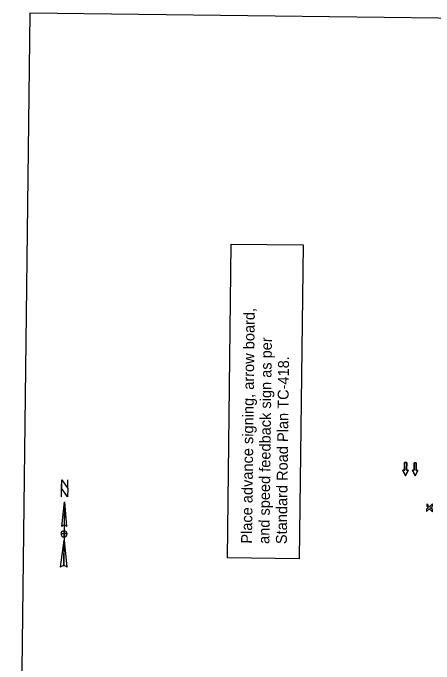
# Model space of a CAD drawing. Extents: x 4959127 to 4960275, y 3872379 to 3884458.
# Drawn here: x 4959256 to 4959738, y 3883713 to 3884458 of the extents above; entities that cross this region are included whole.
import ezdxf

# ---------------------------------------------------------------- set-up
doc = ezdxf.new("R2010")
doc.units = 0
for name, color, linetype in [('Cell', 7, 'Continuous'), ('dsnCellElements', 7, 'Continuous'), ('Level 2', 7, 'Continuous'), ('Level 5', 7, 'Continuous'), ('NamedBoundary', 7, 'Continuous'), ('SheetText', 7, 'Continuous')]:
    doc.layers.add(name, color=color, linetype=linetype)

msp = doc.modelspace()

# ---------------------------------------------------------------- linework, layer by layer
at = {"layer": 'Cell'}
for p, q in [((4959314.62, 3883898.17), (4959313.72, 3883824.93)), ((4959314.62, 3883898.17), (4959317.09, 3883869.97)), ((4959311.46, 3883870.04), (4959311.46, 3883870.04)), ((4959311.57, 3883870.3), (4959312.1, 3883870.88)), ((4959310.19, 3883823.57), (4959314.09, 3883854.51)), ((4959314.13, 3883858.03), (4959314.13, 3883858.03))]:
    msp.add_line(p, q, dxfattribs=at)
for points in [[(4959311.17, 3883903.85), (4959311.41, 3883923.57), (4959318.33, 3883913.62), (4959318.45, 3883923.48)], [(4959311.46, 3883870.04), (4959314.62, 3883898.17), (4959314.29, 3883871.41)], [(4959314.13, 3883858.03), (4959314.17, 3883861.55), (4959310.65, 3883861.6)], [(4959317.69, 3883861.51), (4959314.17, 3883861.55), (4959314.22, 3883865.08)], [(4959313.72, 3883824.93), (4959314.09, 3883854.51), (4959317.23, 3883823.48)]]:
    msp.add_lwpolyline(points, dxfattribs=at)
msp.add_lwpolyline([(4959318.21, 3883903.76), (4959311.29, 3883913.71), (4959311.41, 3883923.57), (4959318.33, 3883913.62)], close=True, dxfattribs=at)
for centre, radius, start, end in [((4959314.25, 3883867.89), 3.52, 89.31793, 142.42328), ((4959314.25, 3883867.89), 3.52, 36.1456, 89.31938), ((4959314.17, 3883861.55), 3.52, 89.29754, 179.29754), ((4959314.17, 3883861.55), 3.52, 179.29754, 269.29754), ((4959314.17, 3883861.55), 3.52, 269.29754, 359.29754), ((4959314.17, 3883861.55), 3.52, 359.29754, 89.29754), ((4959313.66, 3883819.83), 5.1, 89.28693, 132.91649), ((4959313.66, 3883819.83), 5.11, 45.6996, 89.29819)]:
    msp.add_arc(centre, radius, start, end, dxfattribs=at)
at = {"layer": 'dsnCellElements'}
for p, q in [((4959730.05, 3883895.99), (4959729.98, 3883893.24)), ((4959733.34, 3883892.53), (4959730.05, 3883895.99)), ((4959736.8, 3883895.82), (4959733.34, 3883892.53)), ((4959736.73, 3883893.07), (4959736.8, 3883895.82)), ((4959729.82, 3883886.99), (4959733.28, 3883890.28)), ((4959729.89, 3883889.74), (4959729.82, 3883886.99)), ((4959732.19, 3883891.43), (4959729.89, 3883889.74)), ((4959729.98, 3883893.24), (4959732.19, 3883891.43)), ((4959733.28, 3883890.28), (4959736.57, 3883886.82)), ((4959734.44, 3883891.38), (4959736.73, 3883893.07)), ((4959736.64, 3883889.57), (4959734.44, 3883891.38)), ((4959736.57, 3883886.82), (4959736.64, 3883889.57))]:
    msp.add_line(p, q, dxfattribs=at)
at = {"layer": 'Level 2'}
for points in [[(4959704.56, 3883943.18), (4959707.06, 3883943.15), (4959706.96, 3883934.4), (4959708.83, 3883934.38), (4959705.63, 3883928.17), (4959702.58, 3883934.46), (4959704.46, 3883934.43)], [(4959715.57, 3883943.05), (4959718.07, 3883943.02), (4959717.96, 3883934.27), (4959719.83, 3883934.24), (4959716.63, 3883928.03), (4959713.58, 3883934.32), (4959715.46, 3883934.3)]]:
    msp.add_lwpolyline(points, close=True, dxfattribs=at)
at = {"layer": 'Level 5'}
for points in [[(4959704.46, 3883934.43), (4959702.58, 3883934.46), (4959705.63, 3883928.17), (4959708.83, 3883934.38), (4959706.96, 3883934.4), (4959707.06, 3883943.15), (4959704.56, 3883943.18), (4959704.46, 3883934.43)], [(4959715.46, 3883934.3), (4959713.58, 3883934.32), (4959716.63, 3883928.03), (4959719.83, 3883934.24), (4959717.96, 3883934.27), (4959718.07, 3883943.02), (4959715.57, 3883943.05), (4959715.46, 3883934.3)]]:
    msp.add_lwpolyline(points, dxfattribs=at)
at = {"layer": 'NamedBoundary'}
msp.add_lwpolyline([(4959255.6, 3882890.65), (4960255.53, 3882878.39), (4960274.74, 3884445.77), (4959274.82, 3884458.03)], close=True, dxfattribs=at)
at = {"layer": 'SheetText'}
msp.add_lwpolyline([(4959501.41, 3883833.95), (4959505.82, 3884193.44), (4959588.22, 3884192.43), (4959583.81, 3883832.94)], close=True, dxfattribs=at)

# ---------------------------------------------------------------- texts
for s, p in [('Place advance signing, arrow board,', (4959529.62, 3883850.24)), ('and speed feedback sign as per', (4959549.58, 3883850)), ('Standard Road Plan TC-418.', (4959569.55, 3883849.75))]:
    msp.add_text(s, height=12.48, rotation=89.29754, dxfattribs=at).set_placement(p)

doc.saveas('drawing.dxf')
